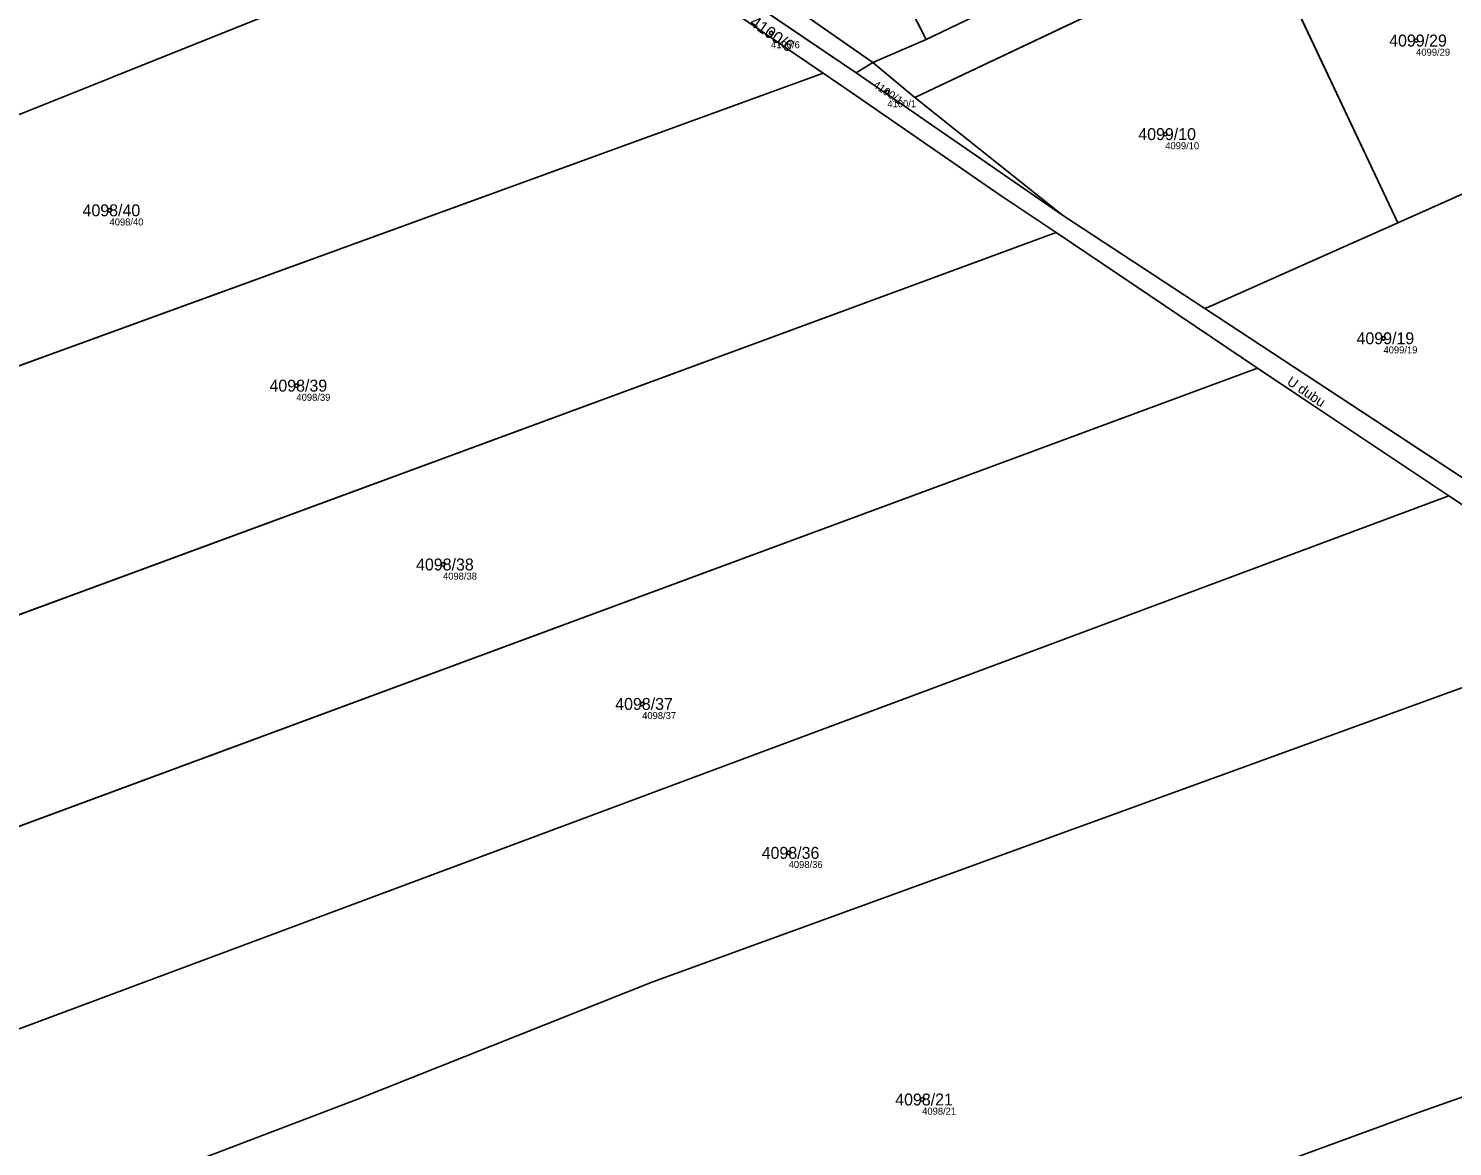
# Model space of a CAD drawing. Extents: x -754150 to -749824, y -1058608 to -1053956.
# Drawn here: x -753404.6 to -753201.7, y -1057324.4 to -1057165.1 of the extents above; entities that cross this region are included whole.
import ezdxf

# ---------------------------------------------------------------- set-up
doc = ezdxf.new("R2010")
doc.units = 0
for name, color, linetype in [('Vrstva 1', 7, 'Continuous'), ('Vrstva 2', 7, 'Continuous'), ('Vrstva 50', 7, 'Continuous'), ('Vrstva 51', 7, 'Continuous'), ('Vrstva 7', 7, 'Continuous')]:
    doc.layers.add(name, color=color, linetype=linetype)

msp = doc.modelspace()

# ---------------------------------------------------------------- linework, layer by layer
at = {"layer": 'Vrstva 1'}
for p, q in [((-753276.72, -1057166.65), (-753296.78, -1057127.19)), ((-753330.07, -1057142.03), (-753286.66, -1057171.38)), ((-753326.47, -1057140.47), (-753284.32, -1057169.95)), ((-753291.37, -1057171.44), (-753328.32, -1057146.22)), ((-753228.98, -1057151.53), (-753278.31, -1057174.91)), ((-753209.51, -1057192.75), (-753228.98, -1057151.53)), ((-753264.5, -1057160.74), (-753276.72, -1057166.65)), ((-753284.32, -1057169.95), (-753276.72, -1057166.65)), ((-753284.32, -1057169.95), (-753286.66, -1057171.38)), ((-753284.32, -1057169.95), (-753278.31, -1057174.91)), ((-753291.37, -1057171.44), (-753474.57, -1057238.12)), ((-753286.66, -1057171.38), (-753257.31, -1057191.69)), ((-753278.31, -1057174.91), (-753257.31, -1057191.69)), ((-753181.59, -1057180.33), (-753209.51, -1057192.75)), ((-753257.31, -1057191.69), (-753237.02, -1057205)), ((-753258.2, -1057194.16), (-753458.7, -1057268.04)), ((-753229.52, -1057213.48), (-753258.2, -1057194.16)), ((-753237.02, -1057205), (-753191.74, -1057234.72)), ((-753229.52, -1057213.48), (-753445.3, -1057293.3)), ((-753202.23, -1057231.67), (-753432.46, -1057317.5))]:
    msp.add_line(p, q, dxfattribs=at)
for points in [[(-753474.57, -1057238.12), (-753489.14, -1057210.64), (-753328.32, -1057146.22)], [(-753258.2, -1057194.16), (-753266.15, -1057188.81), (-753287.47, -1057174.1), (-753291.37, -1057171.44)], [(-753237.02, -1057205), (-753235.88, -1057204.49), (-753209.51, -1057192.75)], [(-753202.23, -1057231.67), (-753223.35, -1057217.63), (-753229.52, -1057213.48)], [(-753175.16, -1057249.86), (-753179.34, -1057246.89), (-753202.23, -1057231.67)], [(-753175.16, -1057249.86), (-753315.64, -1057300.91), (-753357.84, -1057317.7), (-753419.85, -1057341.27)], [(-753394.81, -1057388.49), (-753206.57, -1057319.55), (-753122.18, -1057289.76), (-753112.63, -1057296.09)]]:
    msp.add_lwpolyline(points, dxfattribs=at)
at = {"layer": 'Vrstva 50'}
for centre in [(-753298.8, -1057165.73), (-753206.91, -1057166.8), (-753282.24, -1057174.14), (-753242.65, -1057180.13), (-753393.05, -1057190.99), (-753211.56, -1057209.22), (-753366.42, -1057215.97), (-753345.54, -1057241.45), (-753317.17, -1057261.32), (-753296.3, -1057282.54), (-753277.28, -1057317.68)]:
    msp.add_circle(centre, 0.25, dxfattribs=at)
at = {"layer": 'Vrstva 51'}
for points in [[(-753113.27, -1057089.73), (-753142.06, -1057103.22), (-753170.29, -1057116.46), (-753209.89, -1057135.02), (-753251.64, -1057154.59), (-753264.5, -1057160.74), (-753276.72, -1057166.65), (-753284.32, -1057169.95), (-753278.31, -1057174.91), (-753228.98, -1057151.53), (-753201.31, -1057138.6), (-753174, -1057125.82), (-753147.02, -1057113.2), (-753120.37, -1057100.74), (-753094.05, -1057088.41), (-753067.77, -1057076.41), (-753053.48, -1057069.99), (-753041.94, -1057064.09), (-753016.69, -1057052.1), (-752991.46, -1057040.37), (-752995.32, -1057034.84), (-753028.54, -1057049.51), (-753056.88, -1057063.64), (-753084.96, -1057076.46)], [(-753296.78, -1057127.19), (-753276.72, -1057166.65), (-753264.5, -1057160.74), (-753272.98, -1057142.23), (-753282.96, -1057121.4), (-753288.82, -1057123.97), (-753287.5, -1057127.43), (-753294.58, -1057130.44), (-753295.88, -1057127.03)], [(-753296.78, -1057127.19), (-753303.88, -1057130.72), (-753326.47, -1057140.47), (-753284.32, -1057169.95), (-753276.72, -1057166.65)], [(-753228.98, -1057151.53), (-753209.51, -1057192.75), (-753181.59, -1057180.33), (-753201.31, -1057138.6)], [(-753326.47, -1057140.47), (-753330.07, -1057142.03), (-753286.66, -1057171.38), (-753284.32, -1057169.95)], [(-753291.37, -1057171.44), (-753328.32, -1057146.22), (-753489.14, -1057210.64), (-753474.57, -1057238.12)], [(-753257.31, -1057191.69), (-753237.02, -1057205), (-753235.88, -1057204.49), (-753209.51, -1057192.75), (-753228.98, -1057151.53), (-753278.31, -1057174.91)], [(-753257.31, -1057191.69), (-753278.31, -1057174.91), (-753284.32, -1057169.95), (-753286.66, -1057171.38)], [(-753266.15, -1057188.81), (-753287.47, -1057174.1), (-753291.37, -1057171.44), (-753474.57, -1057238.12), (-753458.7, -1057268.04), (-753258.2, -1057194.16)], [(-753191.17, -1057234.48), (-753163.33, -1057222.56), (-753181.59, -1057180.33), (-753209.51, -1057192.75), (-753235.88, -1057204.49), (-753237.02, -1057205), (-753191.74, -1057234.72)], [(-753258.2, -1057194.16), (-753458.7, -1057268.04), (-753445.3, -1057293.3), (-753229.52, -1057213.48)], [(-753229.52, -1057213.48), (-753445.3, -1057293.3), (-753432.46, -1057317.5), (-753202.23, -1057231.67), (-753223.35, -1057217.63)], [(-753202.23, -1057231.67), (-753432.46, -1057317.5), (-753425.01, -1057331.55), (-753419.85, -1057341.27), (-753357.84, -1057317.7), (-753315.64, -1057300.91), (-753175.16, -1057249.86), (-753179.34, -1057246.89)], [(-753112.63, -1057296.09), (-753130.09, -1057281.84), (-753175.16, -1057249.86), (-753315.64, -1057300.91), (-753357.84, -1057317.7), (-753419.85, -1057341.27), (-753394.81, -1057388.49), (-753206.57, -1057319.55), (-753122.18, -1057289.76)], [(-753112.63, -1057296.09), (-753122.18, -1057289.76), (-753206.57, -1057319.55), (-753394.81, -1057388.49), (-753385.97, -1057405.17), (-753211.77, -1057342.75), (-753135.91, -1057316.6), (-753103.51, -1057303.53)]]:
    msp.add_lwpolyline(points, close=True, dxfattribs=at)
for points in [[(-753425.01, -1057331.55), (-753432.46, -1057317.5), (-753445.3, -1057293.3), (-753458.7, -1057268.04), (-753474.57, -1057238.12), (-753489.14, -1057210.64), (-753328.32, -1057146.22), (-753412.51, -1057089.01), (-753446.59, -1057069.48), (-753482.9, -1057053.95), (-753512.82, -1057060.34), (-753526.28, -1057083.12), (-753544.75, -1057121.28), (-753578.43, -1057141.42), (-753545.2, -1057198.4), (-753476.89, -1057325.29)], [(-753026.79, -1057340.83), (-753068.51, -1057314.67), (-753084.53, -1057310.05), (-753102.91, -1057297.97), (-753125.44, -1057281.07), (-753127.19, -1057279.76), (-753156.99, -1057257.76), (-753168.45, -1057249.34), (-753184.61, -1057239.28), (-753188.23, -1057237.02), (-753191.74, -1057234.72), (-753237.02, -1057205), (-753257.31, -1057191.69), (-753286.66, -1057171.38), (-753330.07, -1057142.03), (-753369.63, -1057111.36), (-753375.55, -1057107.41), (-753397.64, -1057092.72), (-753404.04, -1057088.41), (-753410.08, -1057084.38)], [(-753412.51, -1057089.01), (-753328.32, -1057146.22), (-753291.37, -1057171.44), (-753287.47, -1057174.1), (-753266.15, -1057188.81), (-753258.2, -1057194.16), (-753229.52, -1057213.48), (-753223.35, -1057217.63), (-753202.23, -1057231.67), (-753179.34, -1057246.89), (-753175.16, -1057249.86), (-753130.09, -1057281.84), (-753112.63, -1057296.09), (-753102.2, -1057303), (-753081.6, -1057316.4), (-753062.38, -1057324.92)]]:
    msp.add_lwpolyline(points, dxfattribs=at)

# ---------------------------------------------------------------- texts
at = {"layer": 'Vrstva 2'}
for s, height, rotation, p in [('4100/6', 1.7, 325, (-753301.99, -1057164.53)), ('4100/1', 1.14, 326, (-753284.4, -1057173.37))]:
    msp.add_text(s, height=height, rotation=rotation, dxfattribs=at).set_placement(p)
for s, p in [('4099/29', (-753210.75, -1057167.65)), ('4099/10', (-753246.49, -1057180.98)), ('4098/40', (-753396.89, -1057191.84)), ('4099/19', (-753215.4, -1057210.07)), ('4098/39', (-753370.26, -1057216.82)), ('4098/38', (-753349.38, -1057242.3)), ('4098/37', (-753321.01, -1057262.17)), ('4098/36', (-753300.14, -1057283.39)), ('4098/21', (-753281.12, -1057318.53))]:
    msp.add_text(s, height=1.7, dxfattribs=at).set_placement(p)
at = {"layer": 'Vrstva 50'}
for s, p in [('4100/6', (-753298.8, -1057167.89)), ('4099/29', (-753206.91, -1057168.96)), ('4100/1', (-753282.24, -1057176.3)), ('4099/10', (-753242.65, -1057182.29)), ('4098/40', (-753393.05, -1057193.15)), ('4099/19', (-753211.56, -1057211.38)), ('4098/39', (-753366.42, -1057218.13)), ('4098/38', (-753345.54, -1057243.61)), ('4098/37', (-753317.17, -1057263.48)), ('4098/36', (-753296.3, -1057284.7)), ('4098/21', (-753277.28, -1057319.84))]:
    msp.add_text(s, height=1, dxfattribs=at).set_placement(p)
at = {"layer": 'Vrstva 7'}
msp.add_text('U dubu', height=1.4, rotation=326, dxfattribs=at).set_placement((-753225.44, -1057215.71))

doc.saveas('drawing.dxf')
